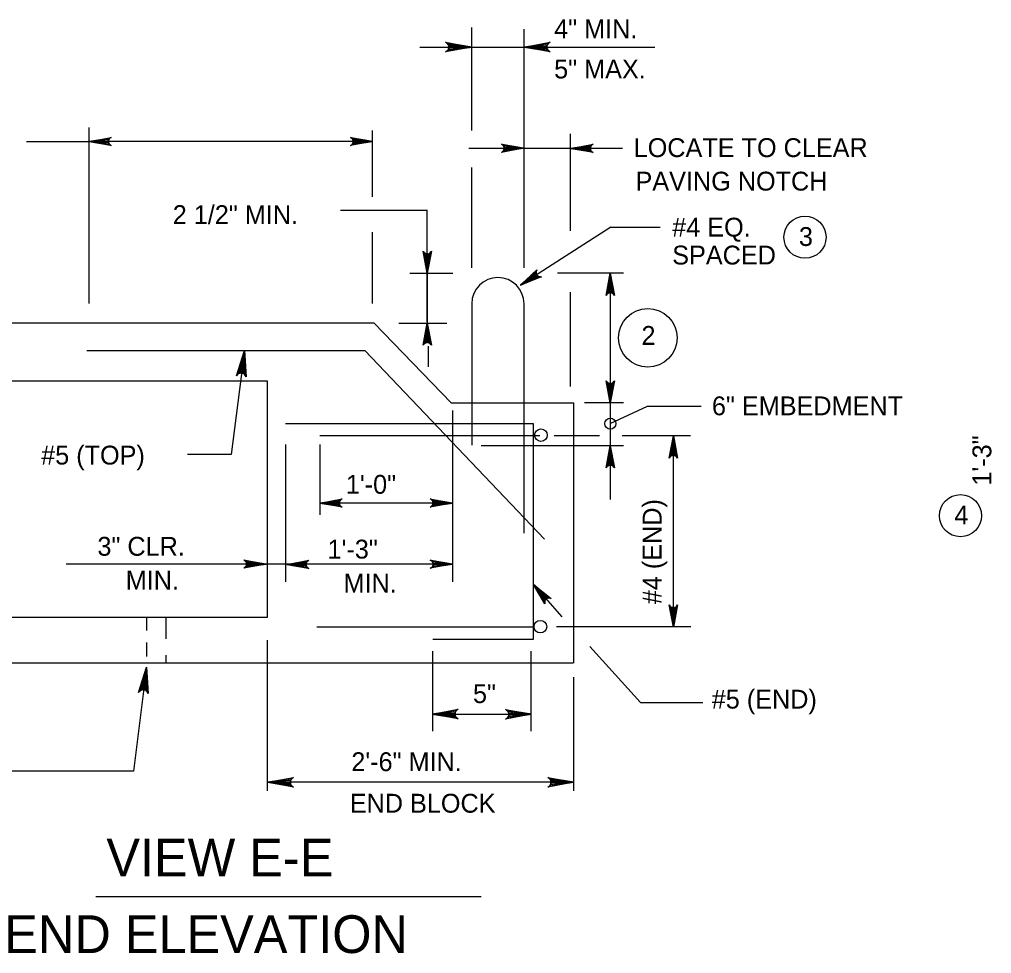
# Model space of a CAD drawing. Extents: x 639331 to 643089, y 299088 to 300975.
# Drawn here: x 641896.4 to 642051.1, y 299387.9 to 299536.6 of the extents above; entities that cross this region are included whole.
import ezdxf

# ---------------------------------------------------------------- set-up
doc = ezdxf.new("R2010")
doc.units = 0
doc.layers.add('1', color=7, linetype='Continuous')

msp = doc.modelspace()

# ---------------------------------------------------------------- linework, layer by layer
at = {"layer": '1'}
for p, q in [((641968.38, 299518.9), (641968.38, 299535.26)), ((641976.71, 299497.01), (641976.71, 299535.02)), ((641960.13, 299532.15), (641968.38, 299532.15)), ((641968.38, 299532.15), (641976.71, 299532.15)), ((641976.71, 299532.15), (641997.48, 299532.15)), ((641907.52, 299491.37), (641907.52, 299519.35)), ((641952.6, 299508.34), (641952.6, 299518.86)), ((641984.1, 299502.91), (641984.1, 299518.37)), ((641967.94, 299516.06), (641992.35, 299516.06)), ((641968.38, 299497.01), (641968.38, 299512.99)), ((641947.49, 299506.2), (641961.3, 299506.2)), ((641961.3, 299488.41), (641961.3, 299506.2)), ((641952.6, 299491.37), (641952.6, 299502.7)), ((641990.52, 299503.5), (641976.14, 299494.26)), ((641990.52, 299503.5), (641998.34, 299503.5)), ((641961.3, 299499.34), (641961.3, 299488.24)), ((641958.52, 299496.16), (641965.38, 299496.16)), ((641992.54, 299496.16), (641982.05, 299496.16)), ((641984.1, 299478.14), (641984.1, 299493.16)), ((641976.71, 299454.82), (641976.71, 299491.32)), ((641952.86, 299488.24), (641881.86, 299488.24)), ((641965.13, 299475.53), (641952.86, 299488.24)), ((641956.78, 299488.24), (641964.43, 299488.24)), ((641907.18, 299483.89), (641951.35, 299483.89)), ((641932.22, 299483.89), (641930.12, 299467.34)), ((641979.95, 299453.88), (641951.35, 299483.89)), ((641961.47, 299484.58), (641961.47, 299481.28)), ((641965.13, 299475.53), (641984.62, 299475.53)), ((641984.62, 299434.11), (641984.62, 299475.53)), ((641992.54, 299475.53), (641986.3, 299475.53)), ((641990.42, 299472.24), (641996.33, 299475.04)), ((641996.33, 299475.04), (642004.87, 299475.04)), ((641978.18, 299472.23), (641938.76, 299472.23)), ((641978.18, 299437.94), (641978.18, 299472.23)), ((641979.23, 299470.28), (641944.24, 299470.28)), ((642000.46, 299439.89), (642000.46, 299470.28)), ((641978.18, 299446.64), (641982.73, 299441.51)), ((641916.66, 299441.42), (641916.66, 299439.35)), ((641919.74, 299441.4), (641919.74, 299438)), ((641943.72, 299439.89), (641978.18, 299439.89)), ((641916.66, 299437.41), (641916.66, 299435.18)), ((641935.89, 299413.83), (641935.89, 299437.79)), ((641962.17, 299437.94), (641978.18, 299437.94)), ((641962.17, 299423.29), (641962.17, 299436.03)), ((641977.83, 299423.29), (641977.83, 299436.03)), ((641987.18, 299436.78), (641995.24, 299427.85)), ((641919.74, 299435.41), (641919.74, 299434.14)), ((641984.45, 299434.11), (641881.86, 299434.11)), ((641916.66, 299433.51), (641914.56, 299416.96)), ((641984.62, 299413.83), (641984.62, 299431.9)), ((641995.24, 299427.85), (642005.16, 299427.85)), ((641969.89, 299396.95), (641908.61, 299396.95))]:
    msp.add_line(p, q, dxfattribs=at)
for points in [[(641968.38, 299532.15), (641964.23, 299531.37), (641964.39, 299531.48), (641964.55, 299531.59), (641964.63, 299531.73), (641964.71, 299531.87), (641964.74, 299532.01), (641964.76, 299532.15), (641964.74, 299532.29), (641964.71, 299532.43), (641964.63, 299532.57), (641964.55, 299532.71), (641964.39, 299532.82), (641964.23, 299532.93), (641968.38, 299532.15), (641964.39, 299532.82), (641964.55, 299532.71), (641968.38, 299532.15), (641964.63, 299532.57), (641964.71, 299532.43), (641968.38, 299532.15), (641964.74, 299532.29), (641964.76, 299532.15), (641968.38, 299532.15), (641964.74, 299532.01), (641964.71, 299531.87), (641968.38, 299532.15), (641964.63, 299531.73), (641964.55, 299531.59), (641968.38, 299532.15), (641964.39, 299531.48)], [(641976.71, 299532.15), (641980.86, 299532.93), (641980.7, 299532.82), (641980.54, 299532.71), (641980.46, 299532.57), (641980.38, 299532.43), (641980.35, 299532.29), (641980.33, 299532.15), (641980.35, 299532.01), (641980.38, 299531.87), (641980.46, 299531.73), (641980.54, 299531.59), (641980.7, 299531.48), (641980.86, 299531.37), (641976.71, 299532.15), (641980.7, 299531.48), (641980.54, 299531.59), (641976.71, 299532.15), (641980.46, 299531.73), (641980.38, 299531.87), (641976.71, 299532.15), (641980.35, 299532.01), (641980.33, 299532.15), (641976.71, 299532.15), (641980.35, 299532.29), (641980.38, 299532.43), (641976.71, 299532.15), (641980.46, 299532.57), (641980.54, 299532.71), (641976.71, 299532.15), (641980.7, 299532.82)], [(641897.57, 299517.13), (641907.52, 299517.13)], [(641907.52, 299517.13), (641911.05, 299517.79), (641910.92, 299517.7), (641910.78, 299517.61), (641910.71, 299517.49), (641910.64, 299517.37), (641910.62, 299517.25), (641910.6, 299517.13), (641910.62, 299517.01), (641910.64, 299516.9), (641910.71, 299516.78), (641910.78, 299516.66), (641910.92, 299516.56), (641911.05, 299516.47), (641907.52, 299517.13), (641910.92, 299516.56), (641910.78, 299516.66), (641907.52, 299517.13), (641910.71, 299516.78), (641910.64, 299516.9), (641907.52, 299517.13), (641910.62, 299517.01), (641910.6, 299517.13), (641907.52, 299517.13), (641910.62, 299517.25), (641910.64, 299517.37), (641907.52, 299517.13), (641910.71, 299517.49), (641910.78, 299517.61), (641907.52, 299517.13), (641910.92, 299517.7)], [(641952.6, 299517.13), (641907.52, 299517.13)], [(641952.6, 299517.13), (641949.07, 299516.47), (641949.2, 299516.56), (641949.34, 299516.66), (641949.41, 299516.78), (641949.48, 299516.9), (641949.5, 299517.01), (641949.52, 299517.13), (641949.5, 299517.25), (641949.48, 299517.37), (641949.41, 299517.49), (641949.34, 299517.61), (641949.2, 299517.7), (641949.07, 299517.79), (641952.6, 299517.13), (641949.2, 299517.7), (641949.34, 299517.61), (641952.6, 299517.13), (641949.41, 299517.49), (641949.48, 299517.37), (641952.6, 299517.13), (641949.5, 299517.25), (641949.52, 299517.13), (641952.6, 299517.13), (641949.5, 299517.01), (641949.48, 299516.9), (641952.6, 299517.13), (641949.41, 299516.78), (641949.34, 299516.66), (641952.6, 299517.13), (641949.2, 299516.56)], [(641976.64, 299516.07), (641973.11, 299515.4), (641973.24, 299515.5), (641973.38, 299515.59), (641973.45, 299515.71), (641973.52, 299515.83), (641973.54, 299515.95), (641973.56, 299516.07), (641973.54, 299516.19), (641973.52, 299516.3), (641973.45, 299516.42), (641973.38, 299516.54), (641973.24, 299516.63), (641973.11, 299516.73), (641976.64, 299516.07), (641973.24, 299516.63), (641973.38, 299516.54), (641976.64, 299516.07), (641973.45, 299516.42), (641973.52, 299516.3), (641976.64, 299516.07), (641973.54, 299516.19), (641973.56, 299516.07), (641976.64, 299516.07), (641973.54, 299515.95), (641973.52, 299515.83), (641976.64, 299516.07), (641973.45, 299515.71), (641973.38, 299515.59), (641976.64, 299516.07), (641973.24, 299515.5)], [(641984.16, 299516.04), (641987.69, 299516.7), (641987.55, 299516.61), (641987.41, 299516.52), (641987.34, 299516.4), (641987.27, 299516.28), (641987.25, 299516.16), (641987.23, 299516.04), (641987.25, 299515.92), (641987.27, 299515.81), (641987.34, 299515.69), (641987.41, 299515.57), (641987.55, 299515.48), (641987.69, 299515.38), (641984.16, 299516.04), (641987.55, 299515.48), (641987.41, 299515.57), (641984.16, 299516.04), (641987.34, 299515.69), (641987.27, 299515.81), (641984.16, 299516.04), (641987.25, 299515.92), (641987.23, 299516.04), (641984.16, 299516.04), (641987.25, 299516.16), (641987.27, 299516.28), (641984.16, 299516.04), (641987.34, 299516.4), (641987.41, 299516.52), (641984.16, 299516.04), (641987.55, 299516.61)], [(641961.3, 299496.16), (641960.64, 299499.69), (641960.73, 299499.55), (641960.83, 299499.42), (641960.95, 299499.35), (641961.06, 299499.28), (641961.18, 299499.26), (641961.3, 299499.24), (641961.42, 299499.26), (641961.54, 299499.28), (641961.66, 299499.35), (641961.77, 299499.42), (641961.87, 299499.55), (641961.96, 299499.69), (641961.3, 299496.16), (641961.87, 299499.55), (641961.77, 299499.42), (641961.3, 299496.16), (641961.66, 299499.35), (641961.54, 299499.28), (641961.3, 299496.16), (641961.42, 299499.26), (641961.3, 299499.24), (641961.3, 299496.16), (641961.18, 299499.26), (641961.06, 299499.28), (641961.3, 299496.16), (641960.95, 299499.35), (641960.83, 299499.42), (641961.3, 299496.16), (641960.73, 299499.55)], [(641976.14, 299494.26), (641978.75, 299496.72), (641978.68, 299496.57), (641978.62, 299496.42), (641978.63, 299496.28), (641978.63, 299496.14), (641978.68, 299496.03), (641978.72, 299495.92), (641978.81, 299495.83), (641978.89, 299495.74), (641979.01, 299495.68), (641979.13, 299495.62), (641979.3, 299495.62), (641979.46, 299495.61), (641976.14, 299494.26), (641979.3, 299495.62), (641979.13, 299495.62), (641976.14, 299494.26), (641979.01, 299495.68), (641978.89, 299495.74), (641976.14, 299494.26), (641978.81, 299495.83), (641978.72, 299495.92), (641976.14, 299494.26), (641978.68, 299496.03), (641978.63, 299496.14), (641976.14, 299494.26), (641978.63, 299496.28), (641978.62, 299496.42), (641976.14, 299494.26), (641978.68, 299496.57)], [(641990.42, 299496.16), (641991.08, 299492.63), (641990.99, 299492.77), (641990.89, 299492.9), (641990.77, 299492.97), (641990.66, 299493.04), (641990.54, 299493.06), (641990.42, 299493.08), (641990.3, 299493.06), (641990.18, 299493.04), (641990.06, 299492.97), (641989.95, 299492.9), (641989.85, 299492.77), (641989.76, 299492.63), (641990.42, 299496.16), (641989.85, 299492.77), (641989.95, 299492.9), (641990.42, 299496.16), (641990.06, 299492.97), (641990.18, 299493.04), (641990.42, 299496.16), (641990.3, 299493.06), (641990.42, 299493.08), (641990.42, 299496.16), (641990.54, 299493.06), (641990.66, 299493.04), (641990.42, 299496.16), (641990.77, 299492.97), (641990.89, 299492.9), (641990.42, 299496.16), (641990.99, 299492.77)], [(641990.42, 299496.16), (641990.42, 299460.16)], [(641968.38, 299491.32), (641968.38, 299468.82)], [(641961.3, 299488.24), (641961.96, 299484.71), (641961.87, 299484.84), (641961.77, 299484.98), (641961.66, 299485.05), (641961.54, 299485.12), (641961.42, 299485.14), (641961.3, 299485.16), (641961.18, 299485.14), (641961.06, 299485.12), (641960.95, 299485.05), (641960.83, 299484.98), (641960.73, 299484.84), (641960.64, 299484.71), (641961.3, 299488.24), (641960.73, 299484.84), (641960.83, 299484.98), (641961.3, 299488.24), (641960.95, 299485.05), (641961.06, 299485.12), (641961.3, 299488.24), (641961.18, 299485.14), (641961.3, 299485.16), (641961.3, 299488.24), (641961.42, 299485.14), (641961.54, 299485.12), (641961.3, 299488.24), (641961.66, 299485.05), (641961.77, 299484.98), (641961.3, 299488.24), (641961.87, 299484.84)], [(641932.22, 299483.89), (641932.48, 299479.67), (641932.39, 299479.84), (641932.3, 299480.02), (641932.17, 299480.11), (641932.05, 299480.21), (641931.91, 299480.25), (641931.77, 299480.3), (641931.63, 299480.29), (641931.49, 299480.28), (641931.34, 299480.22), (641931.2, 299480.15), (641931.07, 299480.01), (641930.94, 299479.86), (641932.22, 299483.89), (641931.07, 299480.01), (641931.2, 299480.15), (641932.22, 299483.89), (641931.34, 299480.22), (641931.49, 299480.28), (641932.22, 299483.89), (641931.63, 299480.29), (641931.77, 299480.3), (641932.22, 299483.89), (641931.91, 299480.25), (641932.05, 299480.21), (641932.22, 299483.89), (641932.17, 299480.11), (641932.3, 299480.02), (641932.22, 299483.89), (641932.39, 299479.84)], [(641935.89, 299479.01), (641881.86, 299479.01)], [(641935.89, 299441.42), (641935.89, 299479.01)], [(641990.42, 299475.53), (641989.76, 299479.06), (641989.85, 299478.93), (641989.95, 299478.79), (641990.06, 299478.72), (641990.18, 299478.65), (641990.3, 299478.63), (641990.42, 299478.61), (641990.54, 299478.63), (641990.66, 299478.65), (641990.77, 299478.72), (641990.89, 299478.79), (641990.99, 299478.93), (641991.08, 299479.06), (641990.42, 299475.53), (641990.99, 299478.93), (641990.89, 299478.79), (641990.42, 299475.53), (641990.77, 299478.72), (641990.66, 299478.65), (641990.42, 299475.53), (641990.54, 299478.63), (641990.42, 299478.61), (641990.42, 299475.53), (641990.3, 299478.63), (641990.18, 299478.65), (641990.42, 299475.53), (641990.06, 299478.72), (641989.95, 299478.79), (641990.42, 299475.53), (641989.85, 299478.93)], [(641965.3, 299474.32), (641965.3, 299447.07)], [(641988.71, 299470.28), (641981.49, 299470.28)], [(642003.2, 299470.28), (641992.3, 299470.28)], [(642000.46, 299470.28), (642001.12, 299466.75), (642001.03, 299466.88), (642000.93, 299467.02), (642000.81, 299467.09), (642000.7, 299467.16), (642000.58, 299467.18), (642000.46, 299467.2), (642000.34, 299467.18), (642000.22, 299467.16), (642000.1, 299467.09), (641999.98, 299467.02), (641999.89, 299466.88), (641999.8, 299466.75), (642000.46, 299470.28), (641999.89, 299466.88), (641999.98, 299467.02), (642000.46, 299470.28), (642000.1, 299467.09), (642000.22, 299467.16), (642000.46, 299470.28), (642000.34, 299467.18), (642000.46, 299467.2), (642000.46, 299470.28), (642000.58, 299467.18), (642000.7, 299467.16), (642000.46, 299470.28), (642000.81, 299467.09), (642000.93, 299467.02), (642000.46, 299470.28), (642001.03, 299466.88)], [(641938.76, 299468.92), (641938.76, 299447.07)], [(641944.24, 299468.92), (641944.24, 299457.71)], [(641992.54, 299468.72), (641969.87, 299468.72)], [(641990.42, 299468.72), (641991.08, 299465.19), (641990.99, 299465.33), (641990.89, 299465.46), (641990.77, 299465.53), (641990.66, 299465.6), (641990.54, 299465.63), (641990.42, 299465.65), (641990.3, 299465.63), (641990.18, 299465.6), (641990.06, 299465.53), (641989.95, 299465.46), (641989.85, 299465.33), (641989.76, 299465.19), (641990.42, 299468.72), (641989.85, 299465.33), (641989.95, 299465.46), (641990.42, 299468.72), (641990.06, 299465.53), (641990.18, 299465.6), (641990.42, 299468.72), (641990.3, 299465.63), (641990.42, 299465.65), (641990.42, 299468.72), (641990.54, 299465.63), (641990.66, 299465.6), (641990.42, 299468.72), (641990.77, 299465.53), (641990.89, 299465.46), (641990.42, 299468.72), (641990.99, 299465.33)], [(641930.12, 299467.34), (641923.16, 299467.34)], [(641944.24, 299459.6), (641947.77, 299460.27), (641947.63, 299460.17), (641947.5, 299460.08), (641947.43, 299459.96), (641947.36, 299459.84), (641947.34, 299459.72), (641947.31, 299459.6), (641947.34, 299459.49), (641947.36, 299459.37), (641947.43, 299459.25), (641947.5, 299459.13), (641947.63, 299459.04), (641947.77, 299458.94), (641944.24, 299459.6), (641947.63, 299459.04), (641947.5, 299459.13), (641944.24, 299459.6), (641947.43, 299459.25), (641947.36, 299459.37), (641944.24, 299459.6), (641947.34, 299459.49), (641947.31, 299459.6), (641944.24, 299459.6), (641947.34, 299459.72), (641947.36, 299459.84), (641944.24, 299459.6), (641947.43, 299459.96), (641947.5, 299460.08), (641944.24, 299459.6), (641947.63, 299460.17)], [(641965.3, 299459.6), (641944.24, 299459.6)], [(641965.3, 299459.6), (641961.77, 299458.94), (641961.91, 299459.04), (641962.05, 299459.13), (641962.12, 299459.25), (641962.19, 299459.37), (641962.21, 299459.49), (641962.23, 299459.6), (641962.21, 299459.72), (641962.19, 299459.84), (641962.12, 299459.96), (641962.05, 299460.08), (641961.91, 299460.17), (641961.77, 299460.27), (641965.3, 299459.6), (641961.91, 299460.17), (641962.05, 299460.08), (641965.3, 299459.6), (641962.12, 299459.96), (641962.19, 299459.84), (641965.3, 299459.6), (641962.21, 299459.72), (641962.23, 299459.6), (641965.3, 299459.6), (641962.21, 299459.49), (641962.19, 299459.37), (641965.3, 299459.6), (641962.12, 299459.25), (641962.05, 299459.13), (641965.3, 299459.6), (641961.91, 299459.04)], [(641965.3, 299449.9), (641903.88, 299449.9)], [(641935.66, 299449.9), (641932.13, 299449.24), (641932.26, 299449.34), (641932.4, 299449.43), (641932.47, 299449.55), (641932.54, 299449.67), (641932.56, 299449.79), (641932.58, 299449.9), (641932.56, 299450.02), (641932.54, 299450.14), (641932.47, 299450.26), (641932.4, 299450.38), (641932.26, 299450.47), (641932.13, 299450.57), (641935.66, 299449.9), (641932.26, 299450.47), (641932.4, 299450.38), (641935.66, 299449.9), (641932.47, 299450.26), (641932.54, 299450.14), (641935.66, 299449.9), (641932.56, 299450.02), (641932.58, 299449.9), (641935.66, 299449.9), (641932.56, 299449.79), (641932.54, 299449.67), (641935.66, 299449.9), (641932.47, 299449.55), (641932.4, 299449.43), (641935.66, 299449.9), (641932.26, 299449.34)], [(641938.95, 299449.83), (641942.48, 299450.49), (641942.34, 299450.4), (641942.21, 299450.3), (641942.14, 299450.19), (641942.07, 299450.07), (641942.05, 299449.95), (641942.03, 299449.83), (641942.05, 299449.71), (641942.07, 299449.59), (641942.14, 299449.48), (641942.21, 299449.36), (641942.34, 299449.26), (641942.48, 299449.17), (641938.95, 299449.83), (641942.34, 299449.26), (641942.21, 299449.36), (641938.95, 299449.83), (641942.14, 299449.48), (641942.07, 299449.59), (641938.95, 299449.83), (641942.05, 299449.71), (641942.03, 299449.83), (641938.95, 299449.83), (641942.05, 299449.95), (641942.07, 299450.07), (641938.95, 299449.83), (641942.14, 299450.19), (641942.21, 299450.3), (641938.95, 299449.83), (641942.34, 299450.4)], [(641965.32, 299449.88), (641961.79, 299449.22), (641961.93, 299449.31), (641962.07, 299449.4), (641962.14, 299449.52), (641962.21, 299449.64), (641962.23, 299449.76), (641962.25, 299449.88), (641962.23, 299450), (641962.21, 299450.11), (641962.14, 299450.23), (641962.07, 299450.35), (641961.93, 299450.44), (641961.79, 299450.54), (641965.32, 299449.88), (641961.93, 299450.44), (641962.07, 299450.35), (641965.32, 299449.88), (641962.14, 299450.23), (641962.21, 299450.11), (641965.32, 299449.88), (641962.23, 299450), (641962.25, 299449.88), (641965.32, 299449.88), (641962.23, 299449.76), (641962.21, 299449.64), (641965.32, 299449.88), (641962.14, 299449.52), (641962.07, 299449.4), (641965.32, 299449.88), (641961.93, 299449.31)], [(641978.18, 299446.64), (641981.02, 299444.44), (641980.86, 299444.48), (641980.7, 299444.52), (641980.56, 299444.49), (641980.43, 299444.47), (641980.32, 299444.4), (641980.22, 299444.34), (641980.15, 299444.25), (641980.07, 299444.15), (641980.03, 299444.02), (641979.99, 299443.89), (641980.01, 299443.73), (641980.03, 299443.56), (641978.18, 299446.64), (641980.01, 299443.73), (641979.99, 299443.89), (641978.18, 299446.64), (641980.03, 299444.02), (641980.07, 299444.15), (641978.18, 299446.64), (641980.15, 299444.25), (641980.22, 299444.34), (641978.18, 299446.64), (641980.32, 299444.4), (641980.43, 299444.47), (641978.18, 299446.64), (641980.56, 299444.49), (641980.7, 299444.52), (641978.18, 299446.64), (641980.86, 299444.48)], [(642000.46, 299439.86), (641999.8, 299443.39), (641999.89, 299443.26), (641999.98, 299443.12), (642000.1, 299443.05), (642000.22, 299442.98), (642000.34, 299442.96), (642000.46, 299442.94), (642000.58, 299442.96), (642000.7, 299442.98), (642000.81, 299443.05), (642000.93, 299443.12), (642001.03, 299443.26), (642001.12, 299443.39), (642000.46, 299439.86), (642001.03, 299443.26), (642000.93, 299443.12), (642000.46, 299439.86), (642000.81, 299443.05), (642000.7, 299442.98), (642000.46, 299439.86), (642000.58, 299442.96), (642000.46, 299442.94), (642000.46, 299439.86), (642000.34, 299442.96), (642000.22, 299442.98), (642000.46, 299439.86), (642000.1, 299443.05), (641999.98, 299443.12), (642000.46, 299439.86), (641999.89, 299443.26)], [(641881.86, 299441.42), (641935.89, 299441.42)], [(642003.22, 299439.89), (641981.84, 299439.89)], [(641916.66, 299433.51), (641916.92, 299429.29), (641916.83, 299429.46), (641916.74, 299429.63), (641916.61, 299429.73), (641916.48, 299429.83), (641916.35, 299429.87), (641916.21, 299429.91), (641916.07, 299429.91), (641915.93, 299429.9), (641915.78, 299429.84), (641915.63, 299429.77), (641915.51, 299429.63), (641915.38, 299429.48), (641916.66, 299433.51), (641915.51, 299429.63), (641915.63, 299429.77), (641916.66, 299433.51), (641915.78, 299429.84), (641915.93, 299429.9), (641916.66, 299433.51), (641916.07, 299429.91), (641916.21, 299429.91), (641916.66, 299433.51), (641916.35, 299429.87), (641916.48, 299429.83), (641916.66, 299433.51), (641916.61, 299429.73), (641916.74, 299429.63), (641916.66, 299433.51), (641916.83, 299429.46)], [(641962.09, 299426.03), (641966.24, 299426.81), (641966.08, 299426.7), (641965.92, 299426.59), (641965.84, 299426.45), (641965.76, 299426.31), (641965.73, 299426.17), (641965.71, 299426.03), (641965.73, 299425.89), (641965.76, 299425.76), (641965.84, 299425.62), (641965.92, 299425.48), (641966.08, 299425.37), (641966.24, 299425.26), (641962.09, 299426.03), (641966.08, 299425.37), (641965.92, 299425.48), (641962.09, 299426.03), (641965.84, 299425.62), (641965.76, 299425.76), (641962.09, 299426.03), (641965.73, 299425.89), (641965.71, 299426.03), (641962.09, 299426.03), (641965.73, 299426.17), (641965.76, 299426.31), (641962.09, 299426.03), (641965.84, 299426.45), (641965.92, 299426.59), (641962.09, 299426.03), (641966.08, 299426.7)], [(641977.91, 299426), (641973.76, 299425.22), (641973.92, 299425.33), (641974.08, 299425.44), (641974.16, 299425.58), (641974.25, 299425.72), (641974.27, 299425.86), (641974.29, 299426), (641974.27, 299426.14), (641974.25, 299426.28), (641974.16, 299426.42), (641974.08, 299426.56), (641973.92, 299426.67), (641973.76, 299426.78), (641977.91, 299426), (641973.92, 299426.67), (641974.08, 299426.56), (641977.91, 299426), (641974.16, 299426.42), (641974.25, 299426.28), (641977.91, 299426), (641974.27, 299426.14), (641974.29, 299426), (641977.91, 299426), (641974.27, 299425.86), (641974.25, 299425.72), (641977.91, 299426), (641974.16, 299425.58), (641974.08, 299425.44), (641977.91, 299426), (641973.92, 299425.33)], [(641977.83, 299425.98), (641962.17, 299425.98)], [(641914.56, 299416.96), (641885.56, 299416.96)], [(641935.89, 299415.17), (641940.04, 299415.95), (641939.88, 299415.83), (641939.72, 299415.72), (641939.64, 299415.58), (641939.56, 299415.45), (641939.54, 299415.31), (641939.51, 299415.17), (641939.54, 299415.03), (641939.56, 299414.89), (641939.64, 299414.75), (641939.72, 299414.61), (641939.88, 299414.5), (641940.04, 299414.39), (641935.89, 299415.17), (641939.88, 299414.5), (641939.72, 299414.61), (641935.89, 299415.17), (641939.64, 299414.75), (641939.56, 299414.89), (641935.89, 299415.17), (641939.54, 299415.03), (641939.51, 299415.17), (641935.89, 299415.17), (641939.54, 299415.31), (641939.56, 299415.45), (641935.89, 299415.17), (641939.64, 299415.58), (641939.72, 299415.72), (641935.89, 299415.17), (641939.88, 299415.83)], [(641984.62, 299415.17), (641980.47, 299414.39), (641980.63, 299414.5), (641980.79, 299414.61), (641980.87, 299414.75), (641980.95, 299414.89), (641980.98, 299415.03), (641981, 299415.17), (641980.98, 299415.31), (641980.95, 299415.45), (641980.87, 299415.58), (641980.79, 299415.72), (641980.63, 299415.83), (641980.47, 299415.95), (641984.62, 299415.17), (641980.63, 299415.83), (641980.79, 299415.72), (641984.62, 299415.17), (641980.87, 299415.58), (641980.95, 299415.45), (641984.62, 299415.17), (641980.98, 299415.31), (641981, 299415.17), (641984.62, 299415.17), (641980.98, 299415.03), (641980.95, 299414.89), (641984.62, 299415.17), (641980.87, 299414.75), (641980.79, 299414.61), (641984.62, 299415.17), (641980.63, 299414.5)], [(641984.62, 299415.17), (641935.89, 299415.17)]]:
    msp.add_lwpolyline(points, dxfattribs=at)
for centre, radius in [((642021.39, 299501.9), 3.35), ((641996.38, 299485.9), 4.66), ((641990.42, 299472.24), 0.886), ((641979.39, 299470.4), 1), ((642046.12, 299457.59), 3.35), ((641979.31, 299439.93), 1)]:
    msp.add_circle(centre, radius, dxfattribs=at)
msp.add_arc((641972.54, 299491.32), 4.16, 0, 180, dxfattribs=at)

# ---------------------------------------------------------------- texts
for s, height, p in [('4" MIN.', 3, (641981.49, 299533.55)), ('5" MAX.', 3, (641981.49, 299527.16)), ('LOCATE TO CLEAR', 3, (641994.14, 299514.65)), ('PAVING NOTCH', 3, (641994.43, 299509.32)), ('2 1/2" MIN.', 3, (641920.82, 299503.99)), ('#4 EQ.', 3, (642000.27, 299502)), ('3', 3, (642020.42, 299500.51)), ('SPACED', 3, (642000.27, 299497.56)), ('2', 3, (641995.38, 299484.77)), ('#5 (TOP)', 3, (641899.89, 299465.73)), ('1\'-0"', 3, (641948.36, 299461.08)), ('4', 3, (642045.16, 299456.2)), ('3" CLR.', 3, (641908.84, 299451.22)), ('1\'-3"', 3, (641945.45, 299450.77)), ('MIN.', 3, (641913.34, 299445.82)), ('MIN.', 3, (641947.99, 299445.37)), ('5"', 3, (641968.58, 299427.78)), ('#5 (END)', 3, (642006.56, 299426.9)), ('2\'-6" MIN.', 3, (641949.23, 299416.95)), ('END BLOCK', 3, (641948.98, 299410.34)), ('VIEW E-E', 6, (641910.26, 299400.2)), (' END ELEVATION', 6, (641891.8, 299388.01))]:
    msp.add_text(s, height=height, dxfattribs=at).set_placement(p)
for s, rotation, p in [('6" EMBEDMENT', 360, (642006.59, 299473.57)), ('1\'-3"', 90, (642051.03, 299462.38)), ('#4 (END)', 90, (641998.58, 299443.51))]:
    msp.add_text(s, height=3, rotation=rotation, dxfattribs=at).set_placement(p)

doc.saveas('drawing.dxf')
